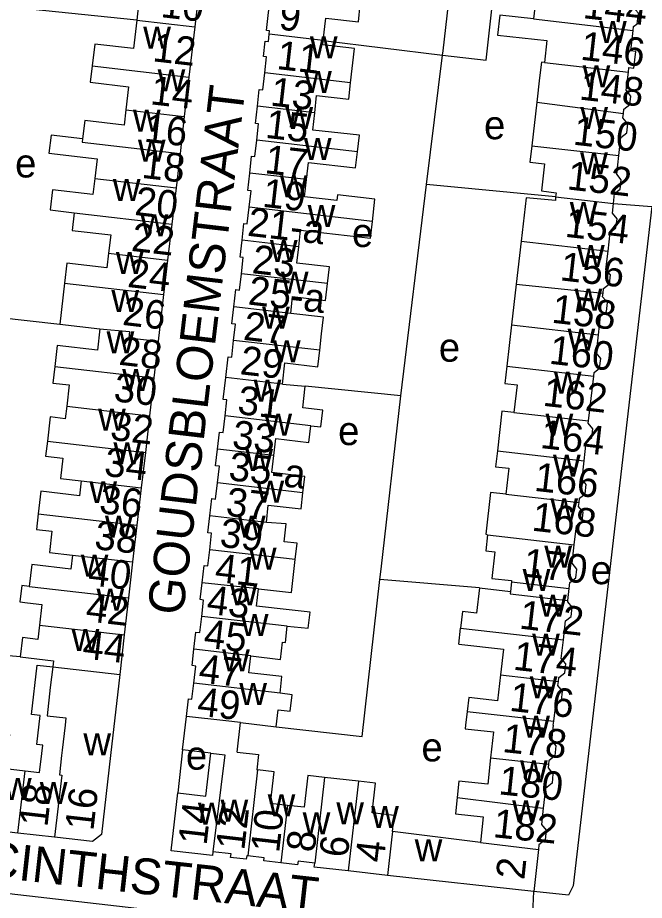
# Model space of a CAD drawing. Extents: x 161258 to 163262, y 380749 to 382054.
# Drawn here: x 162191.7 to 162279.3, y 380975.6 to 381098.8 of the extents above; entities that cross this region are included whole.
import ezdxf

# ---------------------------------------------------------------- set-up
doc = ezdxf.new("R2010")
doc.units = 0
for name, color, linetype in [('BLT_Basislijn', 7, 'Continuous'), ('BLT_Bebouwing', 7, 'Continuous'), ('BLT_Centroide', 7, 'Continuous'), ('BLT_Huisnummer', 7, 'Continuous'), ('BLT_Huisnummer_ tussenligend', 7, 'Continuous'), ('BLT_Huisnummer_reeks', 7, 'Continuous'), ('BLT_Onderdoorgang_en_onderverdeling', 7, 'Continuous'), ('BLT_Onderverdeling_panden', 7, 'Continuous'), ('BLT_Straatnaam', 7, 'Continuous'), ('BLT_Vlakafsluiter', 7, 'Continuous')]:
    doc.layers.add(name, color=color, linetype=linetype)

msp = doc.modelspace()

# ---------------------------------------------------------------- linework, layer by layer
at = {"layer": 'BLT_Basislijn'}
for p, q in [((162234.43, 381095.67), (162251.09, 381093.61)), ((162248.87, 381075.53), (162251.09, 381093.61)), ((162245.24, 381046.03), (162248.87, 381075.53)), ((162266.88, 381073.82), (162248.87, 381075.53)), ((162274.97, 381072.89), (162280.3, 381072.45)), ((162184.44, 381057.54), (162197.62, 381056.03)), ((162245.24, 381046.03), (162231.9, 381047.35)), ((162256.23, 381019.19), (162242.33, 381020.38)), ((162192.1, 381009.56), (162179.02, 381010.75)), ((162214.78, 380996.56), (162214.1, 380990.55)), ((162149.69, 380981.18), (162263.4, 380968.19))]:
    msp.add_line(p, q, dxfattribs=at)
for points in [[(162208.37, 381098.47), (162189.76, 381100.39), (162188.96, 381094.31), (162188.89, 381093.72)], [(162280.3, 381072.45), (162269.33, 380977.56), (162268.66, 380976.26), (162263.86, 380976.81)], [(162242.33, 381020.38), (162242.5, 381021.81), (162245.24, 381046.03)], [(162227.86, 380999.81), (162239.84, 380998.43), (162242.33, 381020.38)]]:
    msp.add_lwpolyline(points, dxfattribs=at)
at = {"layer": 'BLT_Bebouwing'}
for p, q in [((162217.07, 381102.74), (162216.47, 381097.54)), ((162216.47, 381097.54), (162215.66, 381090.55)), ((162215.66, 381090.55), (162215.02, 381085.02)), ((162215.02, 381085.02), (162214.42, 381079.86)), ((162214.42, 381079.86), (162213.87, 381075.09)), ((162213.87, 381075.09), (162213.28, 381070.02)), ((162213.28, 381070.02), (162212.69, 381064.99)), ((162212.69, 381064.99), (162212.13, 381060.16)), ((162212.13, 381060.16), (162211.38, 381053.65)), ((162211.38, 381053.65), (162210.78, 381048.52)), ((162210.78, 381048.52), (162210.17, 381043.24)), ((162271.48, 381042.51), (162272.2, 381048.78)), ((162228.74, 381047.67), (162231.9, 381047.35)), ((162210.17, 381043.24), (162209.58, 381038.12)), ((162209.58, 381038.12), (162209, 381033.16)), ((162209, 381033.16), (162208.4, 381027.94)), ((162208.4, 381027.94), (162207.8, 381022.82)), ((162207.8, 381022.82), (162207.22, 381017.8)), ((162260.72, 381020.06), (162260.56, 381018.7)), ((162256.23, 381019.19), (162260.56, 381018.7)), ((162268.6, 381017.43), (162268.79, 381019.12)), ((162207.22, 381017.8), (162206.62, 381012.64)), ((162253.35, 381011.34), (162253.6, 381013.56)), ((162206.62, 381012.64), (162205.99, 381007.11)), ((162205.99, 381007.11), (162204.71, 380995.78)), ((162214.78, 380996.56), (162215.32, 381001.25)), ((162254.52, 381001.94), (162254.3, 381000)), ((162222.88, 381000.38), (162227.86, 380999.81)), ((162266.55, 381000), (162266.62, 381000.56)), ((162197.97, 380996.55), (162197.88, 380995.77)), ((162191.78, 380984.95), (162186.87, 380985.51)), ((162196.9, 380984.37), (162191.78, 380984.95)), ((162256.38, 380983.63), (162244.09, 380985.18)), ((162264.47, 380982.65), (162263.86, 380976.81)), ((162243.39, 380979.04), (162237.91, 380979.67)), ((162263.86, 380976.81), (162243.39, 380979.04))]:
    msp.add_line(p, q, dxfattribs=at)
for points in [[(162251.09, 381093.61), (162257.18, 381092.92), (162259.66, 381115.1)], [(162251.09, 381093.61), (162251.17, 381094.21), (162253.25, 381112.59)], [(162203.56, 381104.22), (162203.28, 381101.79), (162208.68, 381101.16), (162208.37, 381098.47)], [(162264.44, 381104.24), (162264.12, 381101.49), (162263.8, 381098.66)], [(162277.71, 381097.07), (162277.77, 381097.6), (162278.28, 381098), (162278.44, 381099.45), (162278.04, 381099.95), (162278.35, 381102.65)], [(162226.89, 381096.55), (162226.94, 381097.02), (162226.5, 381097.07), (162227.07, 381102.09)], [(162234.43, 381095.67), (162234.79, 381098.76), (162239.33, 381098.24), (162239.6, 381100.66)], [(162263.8, 381098.66), (162259.07, 381099.21), (162258.75, 381096.42), (162265.66, 381095.63), (162265.31, 381092.59)], [(162208.37, 381098.47), (162207.91, 381094.53), (162202.51, 381095.16), (162202.15, 381092.12)], [(162226.26, 381091.13), (162226.52, 381093.37), (162226.08, 381093.42), (162226.33, 381095.58), (162226.77, 381095.53), (162226.89, 381096.55)], [(162277.04, 381091.24), (162277.11, 381091.87), (162277.81, 381091.79), (162278.08, 381094.13), (162277.38, 381094.21), (162277.71, 381097.07)], [(162238.25, 381089.75), (162238.8, 381094.55), (162234.38, 381095.04), (162234.43, 381095.67)], [(162265.31, 381092.59), (162264.9, 381092.63), (162264.65, 381090.42), (162264.25, 381087.03)], [(162202.15, 381092.12), (162201.89, 381089.82), (162207.23, 381089.2), (162206.85, 381085.96)], [(162276.35, 381085.46), (162276.42, 381086.04), (162277.24, 381086.7), (162277.38, 381087.9), (162276.74, 381088.7), (162277.04, 381091.24)], [(162225.22, 381086.47), (162225.49, 381088.83), (162225.99, 381088.78), (162226.26, 381091.13)], [(162233.23, 381085.55), (162233.5, 381087.96), (162237.98, 381087.44), (162238.25, 381089.75)], [(162225.13, 381081.74), (162225.39, 381084), (162224.95, 381084.05), (162225.22, 381086.47)], [(162264.25, 381087.03), (162263.55, 381080.96)], [(162206.85, 381085.96), (162206.6, 381083.83), (162201.1, 381084.47), (162200.8, 381081.93)], [(162239.21, 381080.12), (162239.47, 381082.41), (162232.95, 381083.15), (162233.23, 381085.55)], [(162275.72, 381079.57), (162276.01, 381082.11), (162276.82, 381082.75), (162276.96, 381084.01), (162276.28, 381084.86), (162276.35, 381085.46)], [(162200.8, 381081.93), (162196.4, 381082.44), (162196.1, 381079.9), (162202.83, 381079.12), (162202.51, 381076.4)], [(162224.15, 381077.12), (162224.42, 381079.49), (162224.87, 381079.44), (162225.13, 381081.74)], [(162263.55, 381080.96), (162263.28, 381078.65), (162265.33, 381078.41), (162264.9, 381074.64), (162266.96, 381074.36), (162266.88, 381073.82)], [(162232.09, 381076.22), (162232.36, 381078.6), (162238.95, 381077.85), (162239.21, 381080.12)], [(162274.97, 381072.89), (162275.13, 381074.27), (162275.9, 381074.88), (162276.05, 381076.2), (162275.42, 381076.99), (162275.72, 381079.57)], [(162224.08, 381072.36), (162224.34, 381074.64), (162223.87, 381074.7), (162224.15, 381077.12)], [(162202.51, 381076.4), (162202.25, 381074.14), (162196.6, 381074.79), (162196.27, 381071.99), (162199.65, 381071.6)], [(162241.29, 381070.39), (162241.65, 381073.49), (162236.41, 381074.09), (162236.33, 381073.32), (162231.82, 381073.83), (162232.09, 381076.22)], [(162266.88, 381073.82), (162266.85, 381073.29), (162262.76, 381073.66), (162262.07, 381067.64)], [(162274.22, 381066.25), (162274.51, 381068.84), (162275.31, 381069.48), (162275.46, 381070.74), (162274.82, 381071.54), (162274.97, 381072.89)], [(162199.65, 381071.6), (162199.36, 381069.11), (162204.74, 381068.49), (162204.45, 381065.95)], [(162223.08, 381067.76), (162223.35, 381070.11), (162223.82, 381070.06), (162224.08, 381072.36)], [(162231.01, 381066.85), (162231.27, 381069.17), (162241.03, 381068.05), (162241.29, 381070.39)], [(162222.99, 381063.06), (162223.26, 381065.34), (162222.81, 381065.39), (162223.08, 381067.76)], [(162235.01, 381061.69), (162235.28, 381064.02), (162230.74, 381064.54), (162231.01, 381066.85)], [(162262.07, 381067.64), (162261.36, 381061.63)], [(162204.45, 381065.95), (162204.21, 381063.88), (162198.6, 381064.53), (162198.28, 381061.76)], [(162273.51, 381060.38), (162273.59, 381061.02), (162274.39, 381061.66), (162274.54, 381062.91), (162273.92, 381063.68), (162274.22, 381066.25)], [(162221.94, 381058.45), (162222.22, 381060.86), (162222.74, 381060.8), (162222.99, 381063.06)], [(162198.28, 381061.76), (162197.62, 381056.03)], [(162229.88, 381057.54), (162230.15, 381059.88), (162234.74, 381059.35), (162235.01, 381061.69)], [(162261.36, 381061.63), (162260.7, 381055.93)], [(162272.87, 381054.54), (162273.17, 381057.16), (162273.98, 381057.8), (162274.12, 381059.04), (162273.45, 381059.87), (162273.51, 381060.38)], [(162221.91, 381053.76), (162222.17, 381056.02), (162221.67, 381056.07), (162221.94, 381058.45)], [(162233.94, 381052.38), (162234.2, 381054.68), (162234.47, 381057.02), (162229.88, 381057.54)], [(162197.62, 381056.03), (162203.23, 381055.39)], [(162260.7, 381055.93), (162260.07, 381050.16)], [(162203.23, 381055.39), (162202.88, 381052.42), (162197.28, 381053.07), (162196.93, 381050.12)], [(162272.2, 381048.78), (162272.26, 381049.27), (162273.02, 381049.88), (162273.18, 381051.25), (162272.58, 381052), (162272.87, 381054.54)], [(162220.8, 381048.58), (162221.13, 381051.47), (162221.65, 381051.41), (162221.91, 381053.76)], [(162228.74, 381047.67), (162229.08, 381050.62), (162233.68, 381050.09), (162233.94, 381052.38)], [(162196.93, 381050.12), (162196.67, 381047.81), (162198.94, 381047.55), (162198.59, 381044.58)], [(162260.08, 381050.17), (162259.8, 381047.76), (162261.5, 381047.57), (162261.06, 381043.71)], [(162220.72, 381043.22), (162220.98, 381045.47), (162220.45, 381045.53), (162220.8, 381048.58)], [(162232.7, 381041.85), (162234.08, 381041.69), (162234.35, 381044.04), (162231.56, 381044.36), (162231.9, 381047.35)], [(162198.59, 381044.58), (162198.39, 381042.83), (162196.28, 381043.08), (162195.89, 381039.71)], [(162219.64, 381038.57), (162219.92, 381040.97), (162220.46, 381040.91), (162220.72, 381043.22)], [(162261.06, 381043.71), (162259.39, 381043.9), (162258.75, 381038.34)], [(162270.86, 381036.95), (162271.16, 381039.55), (162271.95, 381040.18), (162272.09, 381041.42), (162271.45, 381042.22), (162271.48, 381042.51)], [(162227.53, 381037.67), (162227.8, 381040.04), (162232.43, 381039.51), (162232.7, 381041.85)], [(162195.89, 381039.71), (162195.64, 381037.58), (162198.07, 381037.3), (162197.74, 381034.46), (162200.6, 381034.13)], [(162219.64, 381033.86), (162219.91, 381036.18), (162219.38, 381036.24), (162219.64, 381038.57)], [(162258.75, 381038.34), (162258.5, 381036.12), (162260.36, 381035.91), (162259.94, 381032.28)], [(162231.58, 381032.49), (162231.84, 381034.77), (162227.26, 381035.29), (162227.53, 381037.67)], [(162270.17, 381031.1), (162270.24, 381031.72), (162271.02, 381032.35), (162271.17, 381033.65), (162270.57, 381034.4), (162270.86, 381036.95)], [(162200.6, 381034.13), (162200.36, 381032.07), (162194.96, 381032.69), (162194.6, 381029.54)], [(162218.57, 381029.26), (162218.85, 381031.67), (162219.38, 381031.61), (162219.64, 381033.86)], [(162226.48, 381028.35), (162226.75, 381030.74), (162231.32, 381030.22), (162231.58, 381032.49)], [(162259.94, 381032.28), (162257.81, 381032.53), (162257.14, 381026.68), (162257.39, 381026.6)], [(162269.48, 381025.22), (162269.78, 381027.86), (162270.57, 381028.48), (162270.72, 381029.77), (162270.1, 381030.55), (162270.17, 381031.1)], [(162194.6, 381029.54), (162194.35, 381027.37), (162196.53, 381027.11), (162196.19, 381024.16), (162199.41, 381023.79)], [(162218.57, 381024.5), (162218.83, 381026.82), (162218.3, 381026.88), (162218.57, 381029.26)], [(162230.51, 381023.14), (162230.78, 381025.44), (162228.95, 381025.65), (162229.23, 381028.13), (162226.48, 381028.35)], [(162257.39, 381026.6), (162257.13, 381024.36), (162258.38, 381024.22), (162257.96, 381020.53)], [(162268.79, 381019.12), (162268.89, 381019.97), (162269.69, 381020.6), (162269.83, 381021.83), (162269.19, 381022.64), (162269.48, 381025.22)], [(162199.41, 381023.79), (162199.18, 381021.81), (162193.72, 381022.44), (162193.37, 381019.41)], [(162217.51, 381019.91), (162217.79, 381022.34), (162218.31, 381022.28), (162218.57, 381024.5)], [(162225.39, 381019.08), (162229.99, 381018.55), (162230.51, 381023.14)], [(162217.46, 381015.21), (162217.72, 381017.5), (162217.24, 381017.56), (162217.51, 381019.91)], [(162257.96, 381020.53), (162260.73, 381020.21), (162260.72, 381020.06)], [(162193.37, 381019.41), (162192.32, 381019.53), (162192.06, 381017.24), (162193.1, 381017.12), (162195.13, 381016.88), (162194.8, 381014.01)], [(162229.4, 381013.84), (162232.34, 381013.57), (162232.6, 381015.79), (162229.66, 381016.13), (162225.11, 381016.65), (162225.39, 381019.08)], [(162256.23, 381019.19), (162255.82, 381015.65), (162253.86, 381015.88), (162253.6, 381013.56)], [(162267.97, 381011.92), (162268.28, 381014.58), (162269.05, 381015.19), (162269.2, 381016.49), (162268.58, 381017.27), (162268.6, 381017.43)], [(162216.36, 381010.62), (162216.64, 381013.03), (162217.2, 381012.96), (162217.46, 381015.21)], [(162194.8, 381014.01), (162194.57, 381012.01), (162192.41, 381012.26), (162192.1, 381009.56)], [(162224.31, 381009.71), (162228.47, 381009.19), (162228.74, 381011.6), (162229.14, 381011.55), (162229.4, 381013.84)], [(162253.35, 381011.34), (162259.59, 381010.63), (162259.18, 381007.03)], [(162267.27, 381006.1), (162267.34, 381006.7), (162268.15, 381007.35), (162268.29, 381008.58), (162267.68, 381009.35), (162267.97, 381011.92)], [(162216.34, 381005.87), (162216.62, 381008.28), (162216.1, 381008.34), (162216.36, 381010.62)], [(162192.1, 381009.56), (162196.73, 381009.03), (162196.64, 381008.18)], [(162228.39, 381004.49), (162228.66, 381006.82), (162224.04, 381007.35), (162224.31, 381009.71)], [(162195.24, 380997.23), (162194.43, 380997.32), (162194.89, 381001.36), (162193.68, 381001.49), (162194.46, 381008.38), (162196.64, 381008.18)], [(162259.18, 381007.03), (162258.76, 381003.42), (162254.74, 381003.88), (162254.52, 381001.94)], [(162215.32, 381001.25), (162215.61, 381003.72), (162216.09, 381003.66), (162216.34, 381005.87)], [(162266.62, 381000.56), (162266.89, 381002.86), (162267.7, 381003.49), (162267.84, 381004.78), (162267.21, 381005.58), (162267.27, 381006.1)], [(162227.86, 380999.81), (162228.12, 381002.17), (162229.79, 381001.98), (162230.08, 381004.27), (162228.39, 381004.49)], [(162222.4, 380996.25), (162222.88, 381000.38)], [(162254.3, 381000), (162254.25, 380999.53), (162258.19, 380999.11), (162257.8, 380995.45)], [(162188.41, 380998.95), (162190.58, 380998.7), (162190.04, 380993.96), (162192.77, 380993.64)], [(162266.55, 381000), (162266.33, 380997.88), (162266.93, 380997.13), (162266.79, 380995.74), (162265.95, 380995.06), (162265.9, 380994.59)], [(162192.77, 380993.64), (162194.81, 380993.41), (162195.11, 380996.08), (162195.24, 380997.23)], [(162218.73, 380996.1), (162214.78, 380996.56)], [(162204.71, 380995.78), (162203.45, 380984.75), (162202.21, 380983.76), (162196.9, 380984.37)], [(162214.1, 380990.55), (162218.04, 380990.1), (162218.73, 380996.1)], [(162222.4, 380996.25), (162225.38, 380995.91), (162225.13, 380993.8), (162225.26, 380993.79)], [(162257.8, 380995.45), (162257.42, 380991.78), (162253.36, 380992.21), (162253.12, 380989.92)], [(162265.9, 380994.59), (162265.85, 380994.06), (162266.51, 380993.24), (162266.38, 380991.94), (162265.45, 380991.19), (162265.16, 380988.44)], [(162229.41, 380988.82), (162227.05, 380989.09), (162227.56, 380993.52), (162225.26, 380993.79)], [(162234.61, 380992.71), (162232.28, 380992.98), (162231.77, 380988.55), (162229.41, 380988.82)], [(162239.34, 380992.21), (162234.61, 380992.71)], [(162244.09, 380985.18), (162244.35, 380987.41), (162241.27, 380987.76), (162241.74, 380991.93), (162239.34, 380992.21)], [(162219.02, 380982.32), (162218.96, 380981.81), (162213.17, 380982.48), (162214.1, 380990.55)], [(162253.12, 380989.92), (162252.88, 380987.62), (162256.76, 380987.21), (162256.38, 380983.63)], [(162265.16, 380988.44), (162264.92, 380986.17), (162265.57, 380985.37), (162265.43, 380984.01), (162264.54, 380983.3), (162264.47, 380982.65)], [(162223.9, 380981.77), (162223.75, 380981.79), (162223.66, 380981.29), (162221.49, 380981.54), (162221.54, 380982.03), (162219.02, 380982.32)], [(162228.49, 380980.78), (162226.12, 380981.05), (162226.18, 380981.51), (162223.9, 380981.77)], [(162233.23, 380980.76), (162230.9, 380981.03), (162230.84, 380980.51), (162228.49, 380980.78)], [(162237.91, 380979.67), (162233.17, 380980.21), (162233.23, 380980.76)]]:
    msp.add_lwpolyline(points, dxfattribs=at)
at = {"layer": 'BLT_Onderdoorgang_en_onderverdeling'}
msp.add_line((162260.72, 381020.06), (162268.79, 381019.12), dxfattribs=at)
msp.add_lwpolyline([(162260.56, 381018.7), (162260.52, 381018.37), (162268.6, 381017.43)], dxfattribs=at)
at = {"layer": 'BLT_Onderverdeling_panden'}
for p, q in [((162263.8, 381098.66), (162277.71, 381097.07)), ((162208.37, 381098.47), (162216.47, 381097.54)), ((162234.43, 381095.67), (162226.89, 381096.55)), ((162265.31, 381092.59), (162277.04, 381091.24)), ((162202.15, 381092.12), (162215.66, 381090.55)), ((162238.25, 381089.75), (162226.26, 381091.13)), ((162233.23, 381085.55), (162225.22, 381086.47)), ((162264.25, 381087.03), (162276.35, 381085.46)), ((162206.85, 381085.96), (162215.02, 381085.02)), ((162239.21, 381080.12), (162225.13, 381081.74)), ((162263.55, 381080.96), (162275.72, 381079.57)), ((162232.09, 381076.22), (162224.15, 381077.12)), ((162202.51, 381076.4), (162213.87, 381075.09)), ((162266.88, 381073.82), (162274.97, 381072.89)), ((162199.65, 381071.6), (162213.28, 381070.02)), ((162241.29, 381070.39), (162224.08, 381072.36)), ((162231.01, 381066.85), (162223.08, 381067.76)), ((162262.07, 381067.64), (162274.22, 381066.25)), ((162204.45, 381065.95), (162212.69, 381064.99)), ((162235.01, 381061.69), (162222.99, 381063.06)), ((162198.28, 381061.76), (162212.13, 381060.16)), ((162261.36, 381061.63), (162273.51, 381060.38)), ((162229.88, 381057.54), (162221.94, 381058.45)), ((162260.7, 381055.93), (162272.87, 381054.54)), ((162233.94, 381052.38), (162221.91, 381053.76)), ((162196.93, 381050.12), (162210.78, 381048.52)), ((162260.07, 381050.16), (162272.2, 381048.78)), ((162228.74, 381047.67), (162220.8, 381048.58)), ((162198.59, 381044.58), (162210.17, 381043.24)), ((162232.7, 381041.85), (162220.72, 381043.22)), ((162261.06, 381043.71), (162271.48, 381042.51)), ((162195.89, 381039.71), (162209.58, 381038.12)), ((162227.53, 381037.67), (162219.64, 381038.57)), ((162258.75, 381038.34), (162270.86, 381036.95)), ((162200.6, 381034.13), (162209, 381033.16)), ((162231.58, 381032.49), (162219.64, 381033.86)), ((162259.94, 381032.28), (162270.17, 381031.1)), ((162194.6, 381029.54), (162208.4, 381027.94)), ((162226.48, 381028.35), (162218.57, 381029.26)), ((162257.39, 381026.6), (162269.48, 381025.22)), ((162199.41, 381023.79), (162207.8, 381022.82)), ((162230.51, 381023.14), (162218.57, 381024.5)), ((162225.39, 381019.08), (162217.51, 381019.91)), ((162193.37, 381019.41), (162207.22, 381017.8)), ((162229.4, 381013.84), (162217.46, 381015.21)), ((162194.8, 381014.01), (162206.62, 381012.64)), ((162253.6, 381013.56), (162267.97, 381011.92)), ((162224.31, 381009.71), (162216.36, 381010.62)), ((162196.64, 381008.18), (162196.3, 381005.27)), ((162196.64, 381008.18), (162205.99, 381007.11)), ((162259.18, 381007.03), (162267.27, 381006.1)), ((162228.39, 381004.49), (162216.34, 381005.87)), ((162254.52, 381001.94), (162266.62, 381000.56)), ((162198.36, 381000), (162197.97, 380996.55)), ((162257.8, 380995.45), (162265.9, 380994.59)), ((162191.78, 380984.95), (162192.77, 380993.64)), ((162225.26, 380993.79), (162223.9, 380981.77)), ((162234.61, 380992.71), (162233.23, 380980.76)), ((162239.34, 380992.21), (162237.91, 380979.67)), ((162253.12, 380989.92), (162265.16, 380988.44)), ((162229.41, 380988.82), (162228.49, 380980.78)), ((162256.38, 380983.63), (162264.47, 380982.65))]:
    msp.add_line(p, q, dxfattribs=at)
for points in [[(162200.8, 381081.93), (162200.74, 381081.44), (162214.42, 381079.86)], [(162203.23, 381055.39), (162207.37, 381055.01), (162207.29, 381054.13), (162211.38, 381053.65)], [(162196.3, 381005.27), (162195.86, 381001.34), (162198.48, 381001.04), (162198.36, 381000)], [(162222.88, 381000.38), (162220.83, 381000.62), (162215.32, 381001.25)], [(162197.88, 380995.77), (162197.58, 380993.1), (162197.89, 380993.06), (162196.9, 380984.37)], [(162218.73, 380996.1), (162220.69, 380995.88), (162219.02, 380982.32)], [(162244.09, 380985.18), (162243.96, 380984.01), (162243.39, 380979.04)]]:
    msp.add_lwpolyline(points, dxfattribs=at)
at = {"layer": 'BLT_Vlakafsluiter'}
msp.add_line((162263.4, 380968.19), (162263.86, 380976.81), dxfattribs=at)

# ---------------------------------------------------------------- texts
at = {"layer": 'BLT_Centroide'}
for s, p in [('w', (162209.28, 381094.5)), ('w', (162272.95, 381095.31)), ('w', (162232.56, 381093.16)), ('w', (162211.29, 381088.56)), ('w', (162231.76, 381088.34)), ('w', (162270.65, 381089.12)), ('w', (162229.14, 381083.28)), ('w', (162270.34, 381083.31)), ('w', (162207.84, 381082.91)), ('e', (162256.88, 381081.86)), ('w', (162208.54, 381078.75)), ('w', (162231.72, 381078.97)), ('e', (162191.38, 381076.52)), ('w', (162270.31, 381076.94)), ('w', (162228.38, 381073.75)), ('w', (162205.03, 381073.22)), ('w', (162268.86, 381070.03)), ('w', (162232.25, 381069.59)), ('w', (162208.9, 381068.28)), ('e', (162238.44, 381066.81)), ('w', (162226.98, 381064.72)), ('w', (162269.87, 381064)), ('w', (162205.45, 381063.06)), ('w', (162228.51, 381060.31)), ('w', (162204.83, 381057.72)), ('w', (162269.53, 381057.91)), ('w', (162225.88, 381055.41)), ('w', (162204.16, 381051.94)), ('w', (162268.55, 381052.34)), ('w', (162227.4, 381050.72)), ('e', (162250.57, 381050.79)), ('w', (162206.34, 381046.69)), ('w', (162266.64, 381046.34)), ('w', (162224.7, 381045.22)), ('w', (162202.98, 381041.16)), ('w', (162226.2, 381040.44)), ('w', (162265.48, 381040.44)), ('e', (162236.5, 381039.14)), ('w', (162205.12, 381036.44)), ('w', (162223.55, 381035.53)), ('w', (162266.51, 381034.72)), ('w', (162201.76, 381031.03)), ('w', (162225.1, 381031.09)), ('w', (162266.15, 381028.62)), ('w', (162203.94, 381026.19)), ('w', (162222.5, 381026.19)), ('w', (162224.04, 381021.75)), ('w', (162265.31, 381022)), ('w', (162200.55, 381020.78)), ('e', (162271.78, 381019.71)), ('w', (162262.28, 381018.75)), ('w', (162221.38, 381016.75)), ('w', (162202.75, 381016.03)), ('w', (162264.57, 381015.16)), ('w', (162222.91, 381012.47)), ('w', (162199.27, 381010.38)), ('w', (162263.6, 381009.72)), ('w', (162220.3, 381007.56)), ('w', (162263.27, 381003.78)), ('w', (162222.7, 381002.84)), ('w', (162262.23, 380998.28)), ('w', (162200.92, 380995.8)), ('e', (162248.14, 380994.96)), ('e', (162215.24, 380993.81)), ('w', (162261.91, 380992.03)), ('w', (162189.83, 380989.58)), ('w', (162194.83, 380989)), ('w', (162226.66, 380987.31)), ('w', (162216.92, 380986.12)), ('w', (162220.08, 380986.55)), ('w', (162236.25, 380986.19)), ('w', (162260.81, 380986.47)), ('w', (162231.55, 380984.77)), ('w', (162241.12, 380985.66)), ('w', (162247.2, 380981))]:
    msp.add_text(s, height=4, dxfattribs=at).set_placement(p)
at = {"layer": 'BLT_Huisnummer'}
for s, rotation, p in [('10', 353.3891, (162211.62, 381098.93)), ('9', 353.4621, (162228.11, 381097.21)), ('146', 353.476, (162270.25, 381092.98)), ('14', 353.3852, (162210.16, 381086.76)), ('13', 353.4692, (162226.93, 381086.58)), ('150', 353.4718, (162269.22, 381081.12)), ('18', 353.3762, (162208.96, 381076.48)), ('17', 353.4651, (162226.15, 381077.13)), ('154', 353.4772, (162268.08, 381068.25)), ('22', 353.3775, (162207.5, 381066.28)), ('26', 353.3844, (162206.27, 381055.94)), ('158', 353.4786, (162266.22, 381056.25)), ('29', 353.4782, (162222.69, 381049.05)), ('30', 353.3943, (162205.04, 381045.28)), ('162', 353.4706, (162264.99, 381044.65)), ('33', 353.4751, (162221.58, 381038.67)), ('34', 353.3794, (162203.71, 381034.86)), ('166', 353.4774, (162263.79, 381032.77)), ('37', 353.4809, (162220.71, 381029.29)), ('38', 353.3842, (162202.34, 381024.64)), ('41', 353.4673, (162219.17, 381020.06)), ('170', 353.3317, (162262.21, 381020.8)), ('45', 353.4651, (162217.61, 381010.88)), ('44', 353.4984, (162200.67, 381009.36)), ('174', 353.4828, (162260.85, 381007.78)), ('49', 353.4776, (162216.7, 381001.38)), ('178', 353.9691, (162259.35, 380996.28)), ('16', 83.4949, (162202.31, 380985.18)), ('14', 83.4338, (162218.12, 380983.16)), ('182', 353.9811, (162258.04, 380984.39)), ('8', 83.4307, (162233.2, 380982.16)), ('4', 83.4434, (162242.86, 380980.73)), ('2', 83.974, (162262.5, 380978.34))]:
    msp.add_text(s, height=4, rotation=rotation, dxfattribs=at).set_placement(p)
at = {"layer": 'BLT_Huisnummer_ tussenligend'}
for s, rotation, p in [('144', 353.4732, (162270.59, 381098.79)), ('12', 353.3891, (162210.48, 381092.77)), ('11', 353.4621, (162227.81, 381091.68)), ('148', 353.476, (162270.08, 381087.42)), ('16', 353.3852, (162209.3, 381081.54)), ('15', 353.4692, (162226.23, 381082.07)), ('152', 353.4718, (162268.37, 381074.87)), ('20', 353.3762, (162207.97, 381071.3)), ('19', 353.4651, (162225.82, 381072.44)), ('23', 353.4772, (162224.37, 381063.17)), ('156', 353.4772, (162267.39, 381062.17)), ('24', 353.3775, (162206.97, 381061.24)), ('27', 353.4832, (162223.15, 381053.86)), ('28', 353.3844, (162205.76, 381050.38)), ('160', 353.4786, (162265.87, 381050.52)), ('31', 353.4782, (162222.34, 381043.49)), ('32', 353.3943, (162204.54, 381039.9)), ('164', 353.4706, (162264.63, 381038.75)), ('36', 353.3794, (162203.02, 381029.65)), ('168', 353.4774, (162263.45, 381027.21)), ('39', 353.4809, (162219.85, 381024.95)), ('40', 353.3842, (162201.46, 381019.6)), ('43', 353.4673, (162218.03, 381015.6)), ('42', 353.3842, (162201.13, 381014.56)), ('172', 353.3317, (162261.7, 381013.53)), ('47', 353.4651, (162216.9, 381006.02)), ('176', 353.4828, (162260.33, 381002.04)), ('180', 353.9691, (162258.82, 380990.38)), ('18', 83.4949, (162195.89, 380985.71)), ('12', 83.4307, (162223.39, 380982.46)), ('10', 83.4307, (162228.25, 380982.1)), ('6', 83.4434, (162237.82, 380981.42))]:
    msp.add_text(s, height=4, rotation=rotation, dxfattribs=at).set_placement(p)
at = {"layer": 'BLT_Huisnummer_reeks'}
for s, rotation, p in [('21-a', 353.4772, (162223.73, 381068.39)), ('25-a', 353.4832, (162223.82, 381058.79)), ('35-a', 353.4751, (162221.09, 381034.25))]:
    msp.add_text(s, height=4, rotation=rotation, dxfattribs=at).set_placement(p)
at = {"layer": 'BLT_Straatnaam'}
for s, rotation, p in [('GOUDSBLOEMSTRAAT', 83.2417, (162214.82, 381015.24)), ('HYACINTHSTRAAT', 353.6304, (162173.27, 380980.46))]:
    msp.add_text(s, height=5, rotation=rotation, dxfattribs=at).set_placement(p)

doc.saveas('drawing.dxf')
